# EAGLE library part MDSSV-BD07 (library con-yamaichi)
YAMAICHI CONNECTOR
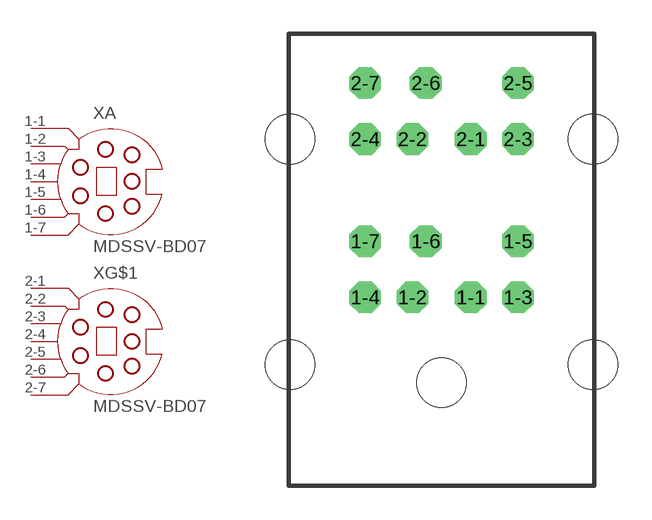
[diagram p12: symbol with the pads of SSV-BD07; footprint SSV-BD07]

Designator prefix X; gates A=SSV-BC07 G$1=SSV-BC07

## MDSSV-BD07 (OC_FARNELL: unknown; OC_NEWARK: unknown)  [SSV-BD07]
1-1  A:1  pas
1-2  A:2  pas
1-3  A:3  pas
1-4  A:4  pas
1-5  A:5  pas
1-6  A:6  pas
1-7  A:7  pas
2-1  G$1:1  pas
2-2  G$1:2  pas
2-3  G$1:3  pas
2-4  G$1:4  pas
2-5  G$1:5  pas
2-6  G$1:6  pas
2-7  G$1:7  pas

## Footprint SSV-BD07 (pad centres in mm)
Mini Din YAMAICHI CONNECTOR
drill 0.9 octagon: 1-1 1.3,8.5; 1-2 -1.3,8.5; 1-3 3.4,8.5; 1-4 -3.4,8.5; 1-5 3.4,11; 1-6 -0.7,11; 1-7 -3.4,11; 2-1 1.3,15.55; 2-2 -1.3,15.55; 2-3 3.4,15.55; 2-4 -3.4,15.55; 2-5 3.4,18.05; 2-6 -0.7,18.05; 2-7 -3.4,18.05
hole 2.2 at -6.75,5.5
hole 2.2 at 0,4.7
hole 2.2 at 6.75,5.5
hole 2.2 at -6.75,15.55
hole 2.2 at 6.75,15.55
